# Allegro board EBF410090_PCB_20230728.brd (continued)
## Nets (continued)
VCC5V0_USB30_HOST: C122.1 C123.1 J15.1(VBUS) J15.10(VBUS) U24.1(OUT)
VCC_1V8: C52.1 C57.1 C58.1 C105.1 J30.245(P245) J30.246(P246) L7.2 R37.1 R38.1 U8.8(VCC)
VCC_12V: C1.1 C2.1 C3.1 C12.1 C13.1 C14.1 C21.1 C22.1 C23.1 C31.1 C32.1 C33.1 C38.1 C165.1 C170.1 C171.1 C172.1 D1.2 F1.2 Q4.3(DRAIN) Q12.3(DRAIN) R7.1 R9.1 R14.1 R23.1 R27.1 R196.1 U3.3(VIN) U4.3(VIN) U5.3(VIN) U36.3(VIN)
VCC_RTC: J30.247(P247) J30.248(P248) R51.2
VCCA_1V8: C53.1 J30.239(P239) J30.240(P240) R35.1 R239.2
VCCIO_ACODEC: C55.1 C186.1 C191.1 J30.241(P241) J30.242(P242) R215.1 R217.1
VDD_3V3: C5.1 C6.1 C59.1 C62.1 C69.1 C75.1 C76.1 C90.1 C94.1 C109.1 C127.1 C431.1 D6.2 D19.2 D20.2 J32.1 J34.1 J35.1 J36.1 L5.2 L6.2 LED1.2(ANODE) LED2.2(ANODE) LED3.2(ANODE) Q7.2(SOURCE) R39.1 R42.1 R44.1 R47.2 R52.1 R53.1 R54.1 R55.1 R67.1 R68.1 R69.1 R70.1 R127.1 R152.1 R156.1 R157.1 R159.1 R164.1 R166.1 R168.1 R170.1 U1.1(OUT) U9.5(VCC) U10.5(VCC) U13.16(VCC) U14.8(VCC) U15.8(VCC)
VDD_5V: C10.1 C11.1 D27.2 Q9.1(GATE) U2.1(OUT)
B_DM1: J15.11(D-) R130.1 U18.5(D2-) U18.6(NC4)
B_DM2: J17.8(D-) R139.1 U20.4(D2+) U20.7(NC3)
B_DM3: J17.2(D-) R132.1 U20.1(D1+) U20.10(NC1)
B_DP1: J15.12(D+) R131.1 U18.4(D2+) U18.7(NC3)
B_DP2: J17.9(D+) R140.1 U20.5(D2-) U20.6(NC4)
B_DP3: J17.3(D+) R133.1 U20.2(D1-) U20.9(NC2)
BD_CH3: C56.1 J30.204(P204) R35.2 R36.1
CAM0_NRST: J20.22 J30.25(P25)
CAM0_PWDN: J20.15 J30.26(P26)
CAM0_PWR_EN: J30.6(P6) R180.1
CAM1_NRST: J21.22 J30.23(P23)
CAM1_PWDN: J21.15 J30.16(P16)
CAM1_PWR_EN: J30.49(P49) R187.1
CC1: D26.2 J16.A5(CC1)
CC2: D26.1 J16.B5(CC2)
CSI_RX_D2N_S0: J20.17 R179.2
CSI_RX_D2N_S1: J21.12 R181.2
CSI_RX_D2P_S0: J20.16 R177.2
CSI_RX_D2P_S1: J21.11 R178.2
CSI_RX_D3N_S0: J20.20 R185.2
CSI_RX_D3N_S1: J21.8 R186.2
CSI_RX_D3P_S0: J20.19 R183.2
CSI_RX_D3P_S1: J21.7 R184.2
CTP0_INT: J18.11 J30.30(P30) R163.2
CTP0_RST: J18.12 J30.34(P34) R167.2
CTP1_INT: J19.11 J30.33(P33) R165.2
CTP1_RST: J19.12 J30.31(P31) R169.2
DBG_RX: R41.2 U10.2(A)
DBG_RXD: J6.3 R41.1 Z3.1
DBG_TX: R40.2 U9.4(Y)
DBG_TXD: J6.2 R40.1 Z2.1
DM4: D35.2 J24.36(USB-D-) R213.1
DP4: D36.2 J24.38(USB-D+) R214.1
DSI0_RST: J18.15 J30.24(P24)
DSI0_TE: J30.22(P22) R161.1
DSI1_RST: J19.15 J30.35(P35)
DSI1_TE: J30.37(P37) R162.1
EDP_AUXN: C157.2 J22.10 R192.2
EDP_AUXP: C156.2 J22.9 R189.2
EDP_BL_EN: J22.22 J30.136(P136)
EDP_BL_PWM: J22.23 J30.167(P167)
EDP_HPDIN_M0: J22.17 J30.45(P45)
EDP_PWR_EN: J30.8(P8) R193.1 R198.1
EDP_TP_INT: J23.2 J30.12(P12) R190.2
EDP_TP_RESET: J23.3 J30.14(P14) R191.2
EDP_TX_AUXN: C157.1 J30.209(P209)
EDP_TX_AUXP: C156.1 J30.211(P211)
EDP_TX_D0N: J22.6 J30.225(P225)
EDP_TX_D0P: J22.7 J30.227(P227)
EDP_TX_D1N: J22.3 J30.221(P221)
EDP_TX_D1P: J22.4 J30.223(P223)
EXT_PWR_EN: J30.231(P231) R1.1 R3.1 R19.1 R24.1
FAN: C30.1 Q1.2(SOURCE) R9.2 R10.2 R12.1
FSPI_CLK: J30.218(P218) U8.6(CLK)
FSPI_CS0N: J30.208(P208) U8.1(C\S\)
FSPI_D0: J5.2 J30.210(P210) U8.5(DI/IO0)
FSPI_D1: J30.212(P212) U8.2(DO/IO1)
FSPI_D2: J30.214(P214) R37.2 U8.3(W\P\/IO2)
FSPI_D3: J30.216(P216) R38.2 U8.7(HOLD/IO3)
GMAC1_INT: J30.43(P43) R112.1
GMAC1_MCLKINOUT_M1: J30.58(P58) R113.1 R115.1
GMAC1_MDC_M1: J30.78(P78) R108.2 U16.13(MDC)
GMAC1_MDIO_M1: J30.76(P76) R109.2 U16.14(MDIO)
GMAC1_RSTN: C86.1 J30.155(P155) R119.2 R120.2 U16.12(PHYRSTB)
GMAC1_RXCLK_M1: J30.82(P82) R95.2 R101.1
GMAC1_RXD0_M1: J30.86(P86) R93.2 R96.1
GMAC1_RXD1_M1: J30.88(P88) R94.2 R97.1
GMAC1_RXD2_M1: J30.90(P90) R99.1 R103.1
GMAC1_RXD3_M1: J30.92(P92) R100.1 R104.1
GMAC1_RXDV_CRS_M1: J30.84(P84) R102.1 R105.1
GMAC1_TXCLK_M1: J30.64(P64) U16.20(TXC)
GMAC1_TXD0_M1: J30.72(P72) U16.18(TXD0)
GMAC1_TXD1_M1: J30.70(P70) U16.17(TXD1)
GMAC1_TXD2_M1: J30.68(P68) U16.16(TXD2)
GMAC1_TXD3_M1: J30.66(P66) U16.15(TXD3)
GMAC1_TXEN_M1: J30.62(P62) U16.19(TXCTL)
GPIO2_B7: J30.17(P17) R48.2
GPIO2_C0: J30.39(P39) R49.2
HDMI_5V: C131.1 D27.1 D32.2 Q10.1(GATE) Q11.1(GATE) R158.1 R160.1 U26.18
HDMI_TX0N_PORT: J30.131(P131) U26.9 U28.4(D2+) U28.7(NC3)
HDMI_TX0P_PORT: J30.133(P133) U26.7 U28.5(D2-) U28.6(NC4)
HDMI_TX1N_PORT: J30.135(P135) U26.6 U27.1(D1+) U27.10(NC1)
HDMI_TX1P_PORT: J30.137(P137) U26.4 U27.2(D1-) U27.9(NC2)
HDMI_TX2N_PORT: J30.139(P139) U26.3 U27.4(D2+) U27.7(NC3)
HDMI_TX2P_PORT: J30.141(P141) U26.1 U27.5(D2-) U27.6(NC4)
HDMI_TX_CEC_PORT: D31.2 Q9.3(DRAIN) U26.13
HDMI_TX_HPD_PORT: D28.2 R154.2 R155.1 U26.19
HDMI_TX_HPDIN: J30.126(P126) R154.1
HDMI_TXCLKN_PORT: J30.127(P127) U26.12 U28.1(D1+) U28.10(NC1)
HDMI_TXCLKP_PORT: J30.129(P129) U26.10 U28.2(D1-) U28.9(NC2)
HDMI_TXDDC_SCL_PORT: D30.2 Q10.3(DRAIN) R158.2 U26.15
HDMI_TXDDC_SDA_PORT: D29.2 Q11.3(DRAIN) R160.2 U26.16
HDMITX_CEC_M0: J30.128(P128) Q9.2(SOURCE) R156.2
HDMITX_SCL: J30.132(P132) Q10.2(SOURCE) R157.2
HDMITX_SDA: J30.130(P130) Q11.2(SOURCE) R159.2
HOST1_DM: J15.2(D-) R136.1 U19.4(D2+) U19.7(NC3)
HOST1_DP: J15.3(D+) R137.1 U19.5(D2-) U19.6(NC4)
HP_DET_L: C187.1 J30.4(P4) R218.1
HP_SNS: J25.1 J26.1 J30.224(P224) R219.1 R221.1
HPL_OUT: C189.1 J30.226(P226)
HPR_OUT: C190.1 J30.222(P222)
HUB_3V3: C128.1 C129.1 C130.1 R145.1 R146.1 R152.2 U22.1(OVCUR#) U22.20(VDD3V3)
HUB_DM1: R130.2 U22.11(DM1)
HUB_DM2: R139.2 U22.9(DM2)
HUB_DM3: R132.2 U22.7(DM3)
HUB_DM4: R213.2 U22.5(DM4)
HUB_DP1: R131.2 U22.12(DP1)
HUB_DP2: R140.2 U22.10(DP2)
HUB_DP3: R133.2 U22.8(DP3)
HUB_DP4: R214.2 U22.6(DP4)
I2C0_SCL_PMIC: J30.154(P154) U12.6(SCL)
I2C0_SDA_PMIC: J30.152(P152) U12.5(SDA)
I2C1_SCL: J18.9 J20.6 J30.150(P150) R164.2
I2C1_SDA: J18.10 J20.5 J30.148(P148) R168.2
I2C2_SCL_M1: J30.55(P55) R222.2
I2C2_SDA_M1: J30.61(P61) R233.2
I2C3_SCL_M0: J30.46(P46) R237.2
I2C3_SDA_M0: J30.44(P44) R238.2
I2C4_SCL_M0: J23.4 J30.57(P57)
I2C4_SDA_M0: J23.5 J30.59(P59)
I2C5_SCL_M0: J19.9 J21.6 J30.42(P42) R166.2
I2C5_SDA_M0: J19.10 J21.5 J30.40(P40) R170.2
LCD0_BL_PWM: J18.13 J30.163(P163)
LCD1_BL_PWM: J19.13 J30.161(P161)
MDIN0_PHY: J14.3(TD1-) U16.2(MDIN0)
MDIN1_PHY: J14.7(RD1-) U16.5(MDIN1)
MDIN2_PHY: J14.6(TD2-) U16.7(MDIN2)
MDIN3_PHY: J14.9(RD2-) U16.10(MDIN3)
MDIP0_PHY: J14.2(TD1+) U16.1(MDIP0)
MDIP1_PHY: J14.4(RD1+) U16.4(MDIP1)
MDIP2_PHY: J14.5(TD2+) U16.6(MDIP2)
MDIP3_PHY: J14.8(RD2+) U16.9(MDIP3)
MIC_INN: C188.2 J27.1 J30.232(P232) R220.1 Z10.2
MIC_INP: C188.1 J26.2 J26.3 J26.4 J26.5 J27.2 J30.230(P230) R216.2 Z7.2
MINIPCIE_3V3: C169.1 C173.1 C174.1 C175.1 C181.1 C182.1 C183.1 C184.1 J24.2(VBAT1) J24.24(VBAT5) J24.39(VBAT2) J24.41(VBAT3) J24.52(VBAT4) L10.2 R203.1 R208.1
MINIPCIE_NWDISABLE: J30.173(P173) R211.2
MIPI0_PWR_EN: J30.10(P10) R172.1
MIPI1_PWR_EN: J30.47(P47) R171.1
MIPI_CSI_RX_CLK0N: J20.10 J30.83(P83)
MIPI_CSI_RX_CLK0P: J20.9 J30.85(P85)
MIPI_CSI_RX_CLK1N: J21.10 J30.79(P79)
MIPI_CSI_RX_CLK1P: J21.9 J30.81(P81)
MIPI_CSI_RX_D0N: J20.12 J30.99(P99)
MIPI_CSI_RX_D0P: J20.11 J30.101(P101)
MIPI_CSI_RX_D1N: J20.8 J30.95(P95)
MIPI_CSI_RX_D1P: J20.7 J30.97(P97)
MIPI_CSI_RX_D2N: J30.91(P91) R179.1 R181.1
MIPI_CSI_RX_D2P: J30.93(P93) R177.1 R178.1
MIPI_CSI_RX_D3N: J30.87(P87) R185.1 R186.1
MIPI_CSI_RX_D3P: J30.89(P89) R183.1 R184.1
MIPI_DSI_TX0_CLKN: J18.24 J30.121(P121)
MIPI_DSI_TX0_CLKP: J18.23 J30.123(P123)
MIPI_DSI_TX0_D0N: J18.27 J30.117(P117)
MIPI_DSI_TX0_D0P: J18.26 J30.119(P119)
MIPI_DSI_TX0_D1N: J18.21 J30.113(P113)
MIPI_DSI_TX0_D1P: J18.20 J30.115(P115)
MIPI_DSI_TX0_D2N: J18.18 J30.109(P109)
MIPI_DSI_TX0_D2P: J18.17 J30.111(P111)
MIPI_DSI_TX0_D3N: J18.30 J30.105(P105)
MIPI_DSI_TX0_D3P: J18.29 J30.107(P107)
MIPI_DSI_TX1_CLKN: J19.24 J30.120(P120)
MIPI_DSI_TX1_CLKP: J19.23 J30.122(P122)
MIPI_DSI_TX1_D0N: J19.27 J30.116(P116)
MIPI_DSI_TX1_D0P: J19.26 J30.118(P118)
MIPI_DSI_TX1_D1N: J19.21 J30.114(P114)
MIPI_DSI_TX1_D1P: J19.20 J30.112(P112)
MIPI_DSI_TX1_D2N: J19.18 J30.108(P108)
MIPI_DSI_TX1_D2P: J19.17 J30.110(P110)
MIPI_DSI_TX1_D3N: J19.30 J30.104(P104)
MIPI_DSI_TX1_D3P: J19.29 J30.106(P106)
OTG0_DM: D33.2 J16.A7(DN1) J16.B7(DN2) R134.1
OTG0_DP: D34.2 J16.A6(DP1) J16.B6(DP2) R135.1
PCIE20_CLKREQN_M0: J30.177(P177) R210.1
PCIE20_PERSTN_M0: J30.175(P175) R212.2
PCIE20_REFCLKN: J24.11(VDD-EXT) J30.181(P181)
PCIE20_REFCLKP: J24.13(RESERVED) J30.183(P183)
PCIE20_RXN: J24.23(UART-RXD) J30.187(P187)
PCIE20_RXP: J24.25(UART-RTS) J30.185(P185)
PCIE20_TXN: C179.1 J30.189(P189)
PCIE20_TXP: C180.1 J30.191(P191)
PCIE20_WAKEN_M0: J30.171(P171) R209.1
PCIE_PWREN_EN: J30.149(P149) R206.1
PE_TXN: C179.2 J24.31(UART-TXD)
PE_TXP: C180.2 J24.33(PERST2)
PHY1_LED1: J14.14(YELA) R116.1 U16.33(LED1)
PHY1_LED2: J14.11(GRLA) R117.1 U16.34(LED2)
PHY_CLKOUT125: R113.2 U16.35(CLKOUT)
PWM2_M0: J30.159(P159) R17.1
PWM3_IR: C64.1 J30.165(P165) R46.1
PWR_3V3_EN: J30.36(P36) R31.1
PWR_5V_EN: J30.140(P140) R33.1
PWR_12V_EN: J30.147(P147) R29.1
PWRON_KEY: C60.1 J30.235(P235) SW1.3(B1) SW1.4(B2) Z1.2
RECOVERY: J30.202(P202) R43.2
RESET_KEY: C61.1 J30.233(P233) SW2.3(B1) SW2.4(B2) Z4.2
RS485_1_A: D23.2 J10.1 R71.2 R80.1 U14.6(A)
RS485_1_B: D21.2 R73.1 R76.1 R79.1 U14.7(B)
RS485_2_A: D24.2 J11.1 R72.2 R82.1 U15.6(A)
RS485_2_B: D22.2 R74.1 R78.1 R81.1 U15.7(B)
RX8010_NIRQ1: J30.20(P20) U12.7(/IRQ1)
RX8010_NIRQ2: J30.18(P18) U12.3(/IRQ2)
RXD1_232: D9.2 R58.1 U13.13(R1IN)
RXD2_232: D8.2 R56.1 U13.8(R2IN)
SARADC_VIN1: J30.200(P200) R232.2
SDMMC0_CLK: J30.178(P178) R63.1
SDMMC0_CMD: J30.176(P176) R62.1
SDMMC0_D0: J30.174(P174) R64.1
SDMMC0_D1: J30.172(P172) R65.1
SDMMC0_D2: J30.170(P170) R60.1
SDMMC0_D3: J30.168(P168) R61.1
SDMMC0_DET_L: J30.166(P166) R66.1
SIM_CLK0: J24.12(USIM-CLK) R202.1
SIM_DATA0: J24.10(USIM-DATA) R204.1
SIM_RST0: J24.14(USIM-RST) R201.1
SIM_VDD: J24.8(USIM-VDD) R200.1 U37.1(VCC) U38.1
SPKN_OUT: J30.236(P236) R224.1 Z13.2
SPKP_OUT: J30.238(P238) R223.1 Z11.2
SS_TXN: C114.1 J15.8(TX-) U19.2(D1-) U19.9(NC2)
SS_TXP: C115.1 J15.9(TX+) U19.1(D1+) U19.10(NC1)
TXD1_232: D11.2 R59.1 U13.14(T1OUT)
TXD2_232: D10.2 R57.1 U13.7(T2OUT)
UART1_DIR: J30.184(P184) R75.1 U14.2(R\E\) U14.3(DE)
UART1_RX_M0: J30.194(P194) R69.2 U14.1(RXD)
UART1_TX_M0: J30.196(P196) R67.2 U14.4(TXD)
UART2_RX_M0_DEBUG: J30.156(P156) R42.2 U10.4(Y)
UART2_TX_M0_DEBUG: J30.158(P158) R39.2 U9.2(A)
UART3_RX_M1: J30.52(P52) R52.2 U13.9(R2OUT)
UART3_TX_M1: J30.54(P54) R53.2 U13.10(T2IN)
UART4_RX_M1: J30.48(P48) R54.2 U13.12(R1OUT)
UART4_TX_M1: J30.50(P50) R55.2 U13.11(T1IN)
UART6_DIR: J30.182(P182) R77.1 U15.2(R\E\) U15.3(DE)
UART6_RX_M0: J30.190(P190) R70.2 U15.1(RXD)
UART6_TX_M0: J30.192(P192) R68.2 U15.4(TXD)
UART7_RX_M0: J30.186(P186) R225.2
UART7_TX_M0: J30.188(P188) R234.2
UART9_RX_M1: J30.98(P98) R235.2
UART9_TX_M1: J30.100(P100) R236.2
USB2_HOST2_DM: J30.7(P7) R126.1
USB2_HOST2_DP: J30.9(P9) R125.1
USB2_HOST3_DM: J30.11(P11) R143.2
USB2_HOST3_DP: J30.13(P13) R142.2
USB3_HOST1_DM: J30.3(P3) R136.2
USB3_HOST1_DP: J30.5(P5) R137.2
USB3_HOST1_SSRXN: J15.5(RX-) J30.201(P201) U18.2(D1-) U18.9(NC2)
USB3_HOST1_SSRXP: J15.6(RX+) J30.199(P199) U18.1(D1+) U18.10(NC1)
USB3_HOST1_SSTXN: C114.2 J30.197(P197)
USB3_HOST1_SSTXP: C115.2 J30.195(P195)
USB20_HOST_PWR_EN: J30.28(P28) R141.1
USB20_OTG_PWR_EN: J30.138(P138) R150.1
USB30_HOST_PWR_EN: J30.41(P41) R147.1
USB OTG: C125.1 C126.1 J16.A4(VBUS1) J16.A9(VBUS2) J16.B4(VBUS4) J16.B9(VBUS3) R149.1 U25.1(OUT)
USB_OTG0_DM: J30.203(P203) R134.2
USB_OTG0_DP: J30.205(P205) R135.2
USB_OTG0_ID: J30.160(P160) R138.2
USB_OTG0_VBUSDET: J30.162(P162) R149.2 R151.1
USER_LED: J30.142(P142) R45.2
WLAN_PWR_EN: J30.151(P151) R128.1
N02088: F1.1 J1.4
N03633: C7.1 U3.6(BOOT)
N03641: C7.2 L1.1 U3.2(SW)
N03801: C8.2 R4.2 R6.1 U3.4(FB)
N28501: C28.1 U5.6(BOOT)
N28533: C28.2 L3.1 U5.2(SW)
N15118698: C4.1 R1.2 U1.4(EN)
N15119063: R2.1 U1.3(ISET)
N15122947: C9.1 R3.2 U2.4(EN)
N15123057: R5.1 U2.3(ISET)
N15599533: R96.2 U16.25(RXD0)
N15599537: R97.2 U16.24(RXD1)
N15599541: R99.2 U16.23(RXD2)
N15599545: R100.2 U16.22(RXD3)
N15599549: R101.2 U16.27(RXC)
N15599553: R102.2 U16.26(RXCTL)
N15599792: R90.2 R91.1 R93.1 R94.1 R95.1
N15600759: R106.2 R107.1 R108.1 R109.1
N15600826: R110.2 R112.2 U16.31(INTB)
N15601838: C83.1 U16.37(XTAL_OUT) Y1.1
N15601846: C84.1 U16.36(XTAL_IN) Y1.3
N15602572: R118.1 U16.32(LED0)
N15602600: R117.2 R121.2 R122.1
N15603170: C85.1 J14.1(CT)
N15605512: R98.1 U16.39(RSET)
N15605755: C79.1 C80.1 R89.1 R92.1 U16.28(DVDD_RG)
N15611443: C118.1 R141.2 U21.4(EN)
N15611553: R144.1 U21.3(ISET)
N15653247: C124.1 R150.2 U25.4(EN)
N15653357: R153.1 U25.3(ISET)
N15653957: C121.1 R147.2 U24.4(EN)
N15654067: R148.1 U24.3(ISET)
N15659726: C18.2 R7.2 R8.1 U3.5(EN)
N15752445: L9.1 U26.G1(20) U26.G2(21) U26.G3(22) U26.G4(23)
N15772454: J19.14 R162.2
N15774097: J18.14 R161.2
N15830872: C190.2 J25.3 J25.5 Z9.2
N15830941: C189.2 J25.2 R218.2 Z8.2
N15838979: J25.4 R217.2
N15851038: C185.1 R215.2 R216.1
N15852295: J29.1 R223.2
N15852481: J29.2 R224.2
N15980269: J10.2 R73.2
N16735828: LED1.1(CATHODE) R45.1
N16735933: LED2.1(CATHODE) R48.1
N16793147: D12.2 J9.1(DAT2) R60.2
N16793149: D16.2 J9.7(DAT0) R64.2
N16793151: D15.2 J9.5(CLK) R63.2
N16793153: D14.2 J9.3(CMD) R62.2
N16793155: D13.2 J9.2(CD/DAT3) R61.2
N16793157: D17.2 J9.8(DAT1) R65.2
N16793300: D18.2 J9.9(CD) R66.2
N16795570: LED3.1(CATHODE) R49.1
N16795883: C37.2 R23.2 R24.2 R25.1 U5.5(EN)
N16811933: J24.1(MIC-P) R208.2 R209.2
N16823854: J24.7(SPK-N) R210.2
N16928945: J24.20(W-DISABLE) R211.1
N16929135: J24.22(PERST1) R212.1
N16980859: C178.1 R201.2 U37.2(RST) U38.6
N16980861: C177.1 R202.2 U37.3(CLK) U38.4
N16980863: C176.1 R200.2 R204.2 U37.7(I/O) U38.5
N17405290: C29.2 R20.2 R22.1 U5.4(FB)
N17423559: C19.1 U4.6(BOOT)
N17423580: C19.2 L2.1 U4.2(SW)
N17423608: C27.2 R14.2 R15.1 U4.5(EN)
N17423737: C20.2 R11.2 R13.1 U4.4(FB)
N17430242: R34.1 U7.3(ISET)
N17430314: C47.1 R33.2 U7.4(EN)
N17443353: R32.1 U6.3(ISET)
N17443371: C41.1 R31.2 U6.4(EN)
N17444423: C38.2 Q4.1(GATE) Q5.1(GATE) Q6.3(COLLECTOR) R27.2
N17444523: Q6.1(BASE) R29.2 R30.1
N17454508: C71.2 U13.1(C1+)
N17454513: C71.1 U13.3(C1-)
N17455367: C72.2 U13.4(C2+)
N17455372: C72.1 U13.5(C2-)
N17455499: C70.1 U13.6(V-)
N17455508: C68.1 U13.2(V+)
N17466585: L4.1 U16.30(REG_OUT)
N17592125: C168.1 U36.6(BOOT)
N17592129: C168.2 L10.1 U36.2(SW)
N17592172: C169.2 R203.2 R205.1 U36.4(FB)
N17592286: R206.2 U36.5(EN)
N17633217: C119.1 U22.3(XOUT) Y2.1
N17633237: C120.2 U22.4(XIN) Y2.3
N17633305: R145.2 U22.16(RESET#/CDP)
N17633317: R146.2 U22.18(PSELF)
N17685591: C165.2 Q12.1(GATE) Q13.1(GATE) Q14.3(COLLECTOR) R196.2
N17685601: Q14.1(BASE) R198.2 R199.1
N17685851: Q13.2(SOURCE) R194.2
N17690217: R195.1 U35.3(ISET)
N17690290: C162.1 R193.2 U35.4(EN)
N17695706: C139.1 R172.2 U29.4(EN) U31.4(EN)
N17695791: R175.1 U31.3(ISET)
N17695827: R174.1 U29.3(ISET)
N17697466: J14.13(YELC) R114.1
N17697880: R182.1 U33.3(ISET)
N17697953: C150.1 R180.2 U33.4(EN)
N17701231: J11.2 R74.2
N17702194: J12.3 R81.2
N17702199: J12.4 R82.2
N17702222: J12.2 R80.2
N17702231: J12.1 R79.2
N17728858: D19.1 R71.1
N17729021: D20.1 R72.1
N17731599: J8.6 R59.2
N17731608: J8.4 R58.2
N17731627: J8.1 R56.2
N17748815: Q5.2(SOURCE) R26.2
N17750545: Q1.1(GATE) Q2.3(COLLECTOR) R12.2
N17750554: D2.1(K) J2.1 Q1.3(DRAIN)
N17750632: Q2.1(BASE) R17.2 R18.1
N17759502: C67.1 D6.3 U12.8(VDD)
N17770939: R142.1 U22.15(DPU)
N17770942: R143.1 U22.14(DMU)
N17861933: C65.1 C66.1 R47.1 U11.2(VCC)
N17863087: R44.2 R46.2 U11.3(OUT)
N17946485: C63.1 R43.1 SW3.3(B1) SW3.4(B2) Z5.2
N17975561: D7.2 J7.1 R50.2 R51.1
N18056005: C109.2 Q7.1(GATE) R127.2 R128.2
N18056634: C106.1 C107.1 U17.2(RF0)
N18056637: C106.2 C108.1 CN1.1
N18057325: R126.2 U17.7(D-)
N18057335: R125.2 U17.6(D+)
N18091011: D6.1 R50.1
N18111918: C136.1 R171.2 U30.4(EN) U32.4(EN)
N18111989: R176.1 U32.3(ISET)
N18112037: R173.1 U30.3(ISET)
N18115454: R188.1 U34.3(ISET)
N18115527: C153.1 R187.2 U34.4(EN)
N18173560: J16.C1(SH1) J16.C2(SH2) J16.C3(SH3) J16.C4(SH4) L8.1
N18175084: D26.3 R138.1
N18245213: LED4.1(CATHODE) Q3.3(COLLECTOR)
N18245628: LED4.2(ANODE) R16.2
N18246356: Q3.1(BASE) R19.2 R21.1
N18288623: C192.1 R232.1 R239.1 SW4.3(B1) SW4.4(B2) Z23.2
N18341998: J14.12(GRLC) R111.1
N18348384: J8.3 R57.2
N18386455: Q12.2(SOURCE) R194.1
N18461230: Q4.2(SOURCE) R26.1
N18494968: D48.2 J34.2 R237.1
N18494970: D47.2 J34.3 R238.1
N18495009: D50.2 J32.2 R222.1
N18495011: D49.2 J32.3 R233.1
N18495097: D52.2 J35.2 R234.1
N18495099: D51.2 J35.3 R225.1
N18495175: D54.2 J36.2 R236.1
N18495177: D53.2 J36.3 R235.1

Pads without a net: J6 1; J15 14 15 17 18; J16 A8 B8; J20 13 14; J21 13 14 16 17 18 19 20 21; J22 1 14 24 25 30; J24 3 5 6 16 17 19 28 30 32 42 44 45 46 47 48 49 51; J30 19 21 27 29 32 51 65 67 69 71 73 75 96 153 213 215 217 219; NOREF#2 1; NOREF#4 1; NOREF#5 1; NOREF#8 1; NOREF#9 1; NOREF#10 1; NOREF#11 1; NOREF#12 1; U12 1 2; U17 3 4 9 10 11 12 13 14; U22 2 13 17 19 21 22 23 24; U26 14; U37 4 6; U38 3

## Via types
v1: diameter 0.508, hole 0.305, TOP to BOTTOM, 1260 vias

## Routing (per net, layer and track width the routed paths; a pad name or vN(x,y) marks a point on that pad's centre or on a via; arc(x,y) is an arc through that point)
1V05_AVDD_PHY: length 27.4
  TOP w0.305: v1(67.94,37.43) 67.91,37.43 67.26,36.78 67.26,34.57 66.65,33.96 63.17,33.96 62.56,34.57 62.56,38.43 61.75,39.23 C100.1 v1(61.72,40.04) 61.02,40.74 60.38,40.74 60.08,41.05 C101.1 ; C101.1 C99.1 59.44,45.46 59.43,45.46 v1(59.4,45.46) ; C101.1 v1(59.4,43.43)
  BOTTOM w0.203: v1(59.4,45.46) 59.44,45.46 59.45,45.45 U16.8 ; U16.3 59.46,43.45 59.44,43.43 v1(59.4,43.43) ; v1(61.72,40.04) 61.72,40.38 61.87,40.53 U16.38
  BOTTOM w0.305: R124.2 v1(67.94,37.43) C102.1
1V05_DVDD_PHY: length 13.1
  TOP w0.305: v1(68.96,37.43) 68.96,37.46 67.31,39.11 67.31,42.95 66.45,43.81 C95.1 C96.1 C97.1 66.41,46.47 v1(66.55,46.61)
  BOTTOM w0.203: v1(66.55,46.61) 66.19,46.25 U16.21
  BOTTOM w0.305: C98.1 v1(68.96,37.43) R123.1
1V8_DVDD_PHY: length 34.9
  ART03 w0.305: v1(59.33,51.56) 66.88,51.56 67.16,51.28 67.16,50.27 v1(66.55,49.66)
  BOTTOM w0.305: L7.1 75.65,48.39 C103.1 ; C103.1 C104.1 R90.1 76.02,46.35 76.33,46.05 76.33,39.42 76.02,39.11 R89.2 ; C103.1 74.41,48.42 73.71,49.12 67.97,49.12 67.44,49.66 v1(66.55,49.66) 66.29,49.66 65.41,50.54 R106.1 ; R119.1 v1(59.33,51.56)
3V3_AVDD_PHY: length 16.8
  TOP w0.305: v1(60.71,40.04) 59.17,40.04 58.67,40.54 58.67,45.59 59.82,46.73 C93.1 59.33,47.49 v1(59.33,48)
  BOTTOM w0.203: v1(59.33,48) 60.45,48 61.06,47.39 U16.11 ; U16.40 61.06,41 60.71,40.64 v1(60.71,40.04)
  BOTTOM w0.305: v1(60.71,40.04) 60.48,40.04 59.56,39.12 C92.1
3V3_DVDD_PHY: length 61.9
  TOP w0.381: R122.2 64.26,35.23 64.57,34.92 v1(65.28,34.92) 65.43,34.92 66.55,36.04 v1(66.55,37.43) 66.55,37.46 66.41,37.6 C88.1 C89.1 66.41,42.79 v1(66.55,42.92)
  ART03 w0.305: v1(66.55,50.67) 66.19,51.03 59.81,51.03 v1(59.33,50.54)
  ART04 w0.305: v1(66.55,42.92) 67.11,43.49 67.11,50.11 v1(66.55,50.67)
  ART04 w0.381: v1(75.18,45.34) 74.63,44.78 74.63,39.83 73.86,39.06 67.31,39.06 66.55,38.3 v1(66.55,37.43)
  BOTTOM w0.203: v1(66.55,42.92) 66.42,43.05 U16.29
  BOTTOM w0.305: R107.2 65.46,51.56 66.34,50.67 v1(66.55,50.67) ; R92.2 75.51,40.13 75.82,40.44 75.82,45.03 75.51,45.34 v1(75.18,45.34) R91.2 ; R118.2 v1(65.28,34.92) 65.91,34.29 69.33,34.29 69.98,34.94 C87.1 70.01,35.69 70.51,36.19 L5.1 ; R110.1 v1(66.55,37.43) ; R120.1 v1(59.33,50.54)
3V3_EDP: length 17.2
  TOP w0.305: v1(63.75,16.25) R190.1 ; R189.1 125.51,22.6 v1(125.45,22.67) ; J22.12 131.36,25.43 v1(131.61,25.68) 131.36,25.93 J22.13 ; R191.1 v1(66.29,16.25)
  ART04 w0.762: 60.01,13.65 J23.1
  BOTTOM w0.508: v1(125.45,22.67) 126.4,22.67 127.01,23.27 127.01,25.07 127.62,25.68 v1(131.61,25.68)
  vias: v1(73.79,17.27) v1(74.8,17.27) v1(132.61,25.68)
3V3_IMAGE_1: length 8.7
  TOP w0.305: R163.1 v1(125.43,69.85) ; J18.5 v1(131.02,66.12)
  ART04 w0.305: v1(125.43,69.85) 125.98,69.29 125.98,66.24 v1(125.35,65.61)
  BOTTOM w0.305: R167.1 130.68,65.78 v1(131.02,66.12)
3V3_IMAGE_2: length 16.5
  TOP w0.203: v1(119.83,48.46) 120.39,49.02 R165.1
  TOP w0.305: C145.1 v1(127.91,43.7) ; R169.1 v1(125.43,47.88)
  ART03 w0.508: v1(125.43,47.88) 126.36,47.88 126.97,47.27 126.97,44.64 v1(127.91,43.7)
  BOTTOM w0.203: v1(125.43,47.88) 124.84,48.46 121.62,48.46 121.11,47.95 120.34,47.95 v1(119.83,48.46)
3V3_OUT: length 7.1
  BOTTOM w0.381: J3.5 2.63,35.82 C43.1 C42.1 7.94,35.75 U6.1
3V3_WLAN: length 7.6
  TOP w0.381: U17.8 95.73,36.64 95.12,36.03 C111.1 C110.1 93.68,35.72 Q7.3
5V0_CAM_1: length 17.6
  TOP w0.381: v1(128.93,58.89) v1(127.93,58.89) 127.46,58.43 C152.1 C151.1 126.12,58.36 U33.1
  ART03 w0.305: v1(128.93,67.55) v1(127.93,67.55) 127.14,67.55 126.53,66.94 126.53,59.5 127.14,58.89 v1(127.93,58.89) v1(128.93,58.89)
5V0_CAM_2: length 0.7
  TOP w0.305: C155.1 v1(127.91,36.33)
  vias: v1(128.91,36.33)
5V_OUT: length 7.1
  BOTTOM w0.305: C49.1 C48.1 7.93,39.69 U7.1
  BOTTOM w0.381: J3.3 2.57,39.63 C49.1
12V_EDP: length 8.4
  TOP w0.305: J22.28 127.88,33.43 ; 127.88,33.93 J22.29 ; J22.26 127.88,32.43 ; J22.27 127.88,32.93
12V_OUT: length 8
  BOTTOM w0.508: Q5.3 8.17,44.07 C39.1 6.65,44.61 C40.1 3.13,44.31 J3.1
GND: length 2698.3
  TOP w0.173: v1(0.79,64.84) v1(0.79,57.22)
  TOP w0.203: v1(27.69,65.53) 28.42,65.53 29.68,64.27 31.35,64.27 31.6,64.51 v1(31.6,64.95) ; v1(125.98,73.79) 125.98,73.02 123.62,70.66 118.86,70.66 J24.54 ; J30.94 v1(57.26,52.58) ; J30.74 v1(62.26,52.58)
  TOP w0.305: J30.102 v1(55.26,52.58) 55.26,51.58 54.61,50.93 54.61,46.14 v1(54.05,45.58) ; J30.146 v1(42.26,52.58) ; R199.2 120.27,28.07 v1(120.27,27.56) ; v1(27.69,65.53) 27.01,64.86 J30.207 v1(27.01,60.78) ; v1(26.91,34.42) 26.91,51.17 27.26,51.52 J30.206 ; v1(4.7,57.33) 5.21,56.82 C18.1 R8.2 ; J24.54 118.85,68.53 117.97,67.66 117.97,66.42 117.57,66.01 117.18,66.01 117.18,66.01 116.22,66.01 116.22,66.01 v1(108.43,66.01) 108.32,66.01 106.91,64.6 106.91,61.77 106.71,61.57 ; J18.16 v1(131.75,71.62) ; v1(39.51,60.78) 39.51,60.78 J30.157 ; J22.16 v1(131.61,27.43) 131.61,27.23 131.3,26.93 J22.15 ; U31.2 v1(123.19,67.44) ; J18.28 v1(131.6,77.62) ; v1(59.76,74.18) 59.72,74.18 55.75,70.2 v1(55.47,70.2) 55.14,70.2 54.84,69.9 54.84,67.49 55.45,66.88 56.62,66.88 57.05,66.45 57.05,64.62 57.02,64.59 ; J22.19 v1(131.61,28.93) ; v1(124.45,25.59) 123.89,25.03 123.89,23.22 v1(124.45,22.67) ; v1(124.45,25.59) 123.56,26.48 Q14.2 ; v1(124.45,25.59) v1(125.45,25.59) 125.51,25.65 R192.1 ; J30.220 v1(23.76,55.55) 22.17,55.55 21.76,55.15 J30.228 ; D30.1 v1(67.4,66.67) ; v1(3.16,45.08) 3.17,45.1 C192.2 ; J30.103 55.01,63.46 55.51,63.96 v1(55.51,64.88) 55.01,65.38 49.94,65.38 49.51,64.95 v1(49.51,63.75) J30.125 ; 128.82,73.4 129.1,73.12 J18.19 v1(131.75,73.12) ; 128.82,73.4 128.63,73.21 127.55,73.21 127.22,72.89 127.22,72.59 124.02,69.39 121.37,69.39 119.2,67.22 119.2,65.58 118.34,64.72 115.11,64.72 114.8,64.41 ; 128.82,73.4 128.82,74.59 v1(128.86,74.62) ; 97.23,89.21 97.26,89.19 97.26,88.19 96.8,87.73 95.5,87.73 95.25,87.48 v1(95.25,83.69) v1(93.6,83.69) v1(91.69,83.69) 90.13,82.13 J15.4 89.82,80.37 87.06,77.61 J15.20 86.39,76.02 86.39,73.43 v1(86.92,72.9) ; R176.2 v1(127.91,44.7) ; J24.18 v1(106,61.57) 106.71,61.57 ; J30.144 v1(44.76,52.58) ; 106.71,61.57 106.83,61.44 106.83,57.19 106.47,56.82 100.3,56.82 99.94,57.19 v1(99.94,58.7) D35.1 ; R115.2 63.86,42.66 v1(63.86,43.45) ; v1(128.86,74.62) 128.86,77.87 128.06,78.67 128.06,79.53 v1(128.65,80.12) ; v1(128.86,74.62) J18.22 ; 1.2,55.63 Z5.1 C63.2 ; J30.134 v1(47.26,52.58) v1(47.26,51.58) 47.26,50.19 47.57,49.88 51.08,49.88 51.38,49.58 v1(51.38,48.83) 50.83,48.27 50.83,46.48 v1(51.38,45.92) ; J19.8 v1(131.55,45.53) ; J30.234 20.26,56.72 v1(20.32,56.78) ; C100.2 61.72,37.59 61.59,37.46 v1(61.59,37.43) ; J24.29 v1(101.6,69.77) ; v1(98.4,72.77) 97.77,73.4 96.64,73.4 v1(96,72.77) ; v1(98.4,72.77) 99.04,73.4 101.77,73.4 v1(102.4,72.77) ; v1(98.4,72.77) J24.37 ; v1(19.81,64.51) 19.51,64.22 J30.237 ; J30.53 67.51,61.07 67.94,60.64 67.94,60.35 v1(68.51,59.78) ; v1(123.19,62.61) U29.2 v1(125.35,62.61) ; v1(114.8,61.57) J24.4 114.8,64.41 ; v1(89.17,88.39) 89.17,89.17 89.13,89.21 ; J19.28 128.92,55.53 v1(128.91,55.51) 128.89,55.53 v1(120.14,55.53) ; J30.2 v1(80.26,52.65) 86.79,52.65 v1(87.33,53.19) v1(91.62,53.19) 92.4,53.97 C184.2 v1(93.13,58.17) ; D52.1 v1(98.17,19.18) ; C56.2 v1(27.56,48.98) ; v1(23.35,35.45) 23.37,35.46 v1(23.37,37.46) ; v1(131.63,52.39) 131.5,52.53 J19.22 v1(128.91,52.53) v1(120.14,52.53) ; v1(124.45,22.67) 125.19,21.93 J22.5 ; v1(124.45,22.67) 123.75,21.96 123.75,20.02 124.05,19.71 v1(124.46,19.71) 125.17,20.43 J22.2 ; C53.2 v1(27.56,43.16) ; v1(59.82,78.1) 59.82,77.97 57.62,75.78 57.62,75.45 55.93,73.76 v1(55.47,73.76) ; U28.8 v1(53.34,71.98) ; J30.180 v1(33.76,52.58) ; U17.5 v1(100.69,27.81) ; 85.67,62.74 85.72,62.69 v1(85.72,61.43) ; 85.67,62.74 v1(82.04,62.74) ; 85.67,62.74 87.63,64.7 87.63,68.75 J24.53 v1(89.55,73.39) 95.38,73.39 v1(96,72.77) ; J30.15 77.01,63.75 v1(77.01,63.75) 78.59,63.75 80.37,65.53 84.33,65.53 85.26,66.46 85.26,74.23 84.22,75.27 84.22,77.33 J14.15 87.06,81.59 J15.19 88.29,82.37 91.01,85.09 93,85.09 v1(93.6,85.69) 93.6,87.1 92.99,87.71 92.99,89.19 92.96,89.21 ; v1(125.45,37.21) U34.2 v1(123.18,37.21) ; R188.2 v1(127.91,38.33) ; J22.18 v1(128.74,28.43) ; v1(4.19,59.16) 4.26,59.09 SW3.2 ; Z23.1 v1(2.16,45.08) ; v1(4.19,63.78) C37.1 ; R220.2 v1(41.27,64.9) ; v1(86.92,72.9) 86.39,72.36 86.39,65.46 85.09,64.16 80.82,64.16 80.51,63.85 v1(80.51,63.75) 80.51,63.75 J30.1 ; v1(86.92,72.9) 86.92,73.11 88.61,74.8 92.76,74.8 J15.16 94.51,74.79 98.3,74.79 J15.21 102.6,79.08 102.6,83.8 98.54,87.86 v1(98.54,88.38) ; v1(101.73,88.39) 101.73,86.61 103.89,84.45 103.89,74.25 v1(102.4,72.77) ; J30.198 v1(29.26,52.58) ; R151.2 v1(38.35,48.98) ; J22.21 v1(131.61,29.93) ; v1(26.41,88.87) 26.41,88.38 v1(29.31,85.47) 29.84,86 33.89,86 v1(34.21,85.67) 33.88,85.35 33.88,76.25 v1(34.21,75.92) 34.21,68.9 v1(33.51,68.21) 33.51,67.55 31.6,65.63 v1(31.6,64.95) ; C27.1 R15.2 ; D31.1 v1(67.4,65.4) 67.51,65.29 ; J30.77 61.51,60.78 v1(61.51,60.78) ; D51.1 v1(100.2,19.18) ; U30.2 v1(125.45,40.51) ; R36.2 v1(27.56,46.57) ; v1(120.14,51.03) v1(128.91,51.03) J19.19 v1(131.57,51.03) ; v1(96,72.77) J24.43 ; J30.56 v1(66.76,52.58) ; D48.1 v1(86.49,17.65) ; v1(29.42,88.87) 29.42,87.72 30.02,87.13 34.73,87.13 35.44,86.41 35.44,85.77 v1(35.54,85.67) 35.44,85.57 35.44,82.11 v1(36.02,81.53) 35.44,80.96 35.44,76.02 v1(35.54,75.92) 35.44,75.82 35.44,67.18 v1(34.01,65.75) 33.45,65.19 33.45,64.31 v1(34.01,63.75) J30.179 ; Z10.1 v1(42.03,68.2) ; J30.193 30.51,61.07 30.57,61.01 30.57,59.34 v1(30.01,58.78) ; J30.261 80.11,45.35 v1(78.24,45.35) ; J22.11 v1(128.74,24.93) ; v1(114.97,58.17) C183.2 ; v1(53.34,75.49) U27.8 U27.3 v1(55.63,75.49) 55.65,75.49 56.62,76.45 56.62,81.18 v1(56.9,81.46) ; J30.164 v1(37.76,52.58) ; J18.25 v1(131.75,76.12) ; C1.2 v1(16.64,72.97) ; C120.1 126.82,77.47 127.13,77.16 127.13,74.99 126.82,74.69 Y2.2 125.99,73.79 v1(125.98,73.79) 125.86,73.66 122.99,73.66 122.68,73.96 122.68,75.31 123.56,76.19 Y2.4 123.33,76.55 C119.2 123.33,77.84 v1(122.94,78.23) ; J22.8 v1(131.22,23.43) ; v1(118.83,48.46) 120.11,49.74 128.69,49.74 v1(128.91,49.53) J19.16 131.07,49.53 v1(131.57,50.03) ; D36.1 v1(96.91,58.7) 96.91,56.81 98.03,55.69 107.21,55.69 108.43,56.91 v1(108.43,57.45) 108.43,64.34 108.81,64.72 114.5,64.72 114.8,64.41 ; v1(42.51,60.78) 42.51,60.78 J30.145 ; J22.20 v1(128.74,29.43) ; v1(102.4,72.77) J24.27 ; v1(56.95,82.78) 55.85,82.78 55.24,82.17 55.24,77.7 54.64,77.09 v1(53.44,77.09) 53.43,77.1 52.82,77.1 45.01,69.29 v1(45.01,63.75) J30.143 ; v1(120.14,57.03) 132.01,57.03 v1(132.38,57.4) ; D29.1 v1(67.4,69.21) ; J30.169 v1(36.51,60.78) ; J24.21 v1(104.8,72.77) ; J24.9 v1(112.8,72.77) ; CN1.2 v1(106.28,19.05) ; C136.2 v1(124.31,42.92) ; CN1.3 v1(103.27,19.05) ; Z1.1 C60.2 ; J30.38 v1(71.26,52.58) ; v1(21.51,60.78) J30.229 21.51,64.22 v1(21.81,64.51) ; J30.124 v1(49.76,55.55) ; C138.2 v1(127.91,40.63) ; v1(59.92,76.4) 59.81,76.4 58.8,75.4 58.8,74.93 55.85,71.98 v1(55.63,71.98) U28.3 ; C153.2 v1(116.46,38.16) ; J24.15 v1(110.4,72.77) ; J24.50 v1(93.2,61.57) ; J24.40 v1(97.2,61.57) ; J30.63 65.01,60.78 v1(65.01,60.78) ; J30.251 v1(16.01,64.01) ; J24.35 v1(99.2,69.77) ; C145.2 v1(127.91,42.7) ; v1(102.27,58.17) C181.2 ; Z7.1 C186.2 v1(37.2,67.44) 37.2,66.67 C185.2 ; C155.2 v1(127.91,37.33) ; J24.34 v1(99.6,61.57) ; D50.1 v1(76.58,16) ; D47.1 v1(87.76,17.65) ; v1(120.14,54.03) J19.25 ; Z4.1 C61.2 ; D28.1 v1(67.4,67.94) ; J19.6 v1(131.55,44.53) ; C150.2 v1(116.75,60.26) ; D49.1 v1(81.06,16) ; J24.26 v1(102.8,61.57)
  TOP w0.381: v1(132.38,57.4) 132.68,57.7 J19.31 v1(132.68,59.89) ; 98.55,89.21 98.55,88.39 v1(98.54,88.38) ; J22.31 v1(132.68,35.15) ; J22.32 v1(132.68,19.21) ; v1(85.09,19.43) v1(85.09,18.29) C431.2 ; U11.1 v1(122.95,10.3) ; SW4.1 5.34,53.59 ; v1(132.68,41.31) J19.32 v1(132.68,38.44) ; v1(101.73,88.39) 101.73,89.21 ; SW4.2 5.35,49.29 ; U11.4 v1(126.76,10.3)
  TOP w0.508: U32.2 120.88,45.34 v1(120.83,45.39) v1(119.83,45.39) ; v1(67.37,89.21) v1(66.37,89.21) v1(65.37,89.21) v1(61.56,89.21) v1(57.75,89.21) v1(53.94,89.21) v1(50.13,89.21) v1(46.32,89.21) v1(42.51,89.21) v1(38.7,89.21) v1(34.89,89.21) ; 3.05,26.57 J6.4 ; J6.4 2.14,27.47 ; J6.4 3.05,28.37 ; J6.4 3.95,27.47 ; J3.6 2.51,34.42 ; J3.6 2.51,32.97 ; J3.6 1.78,33.69 ; J3.6 3.24,33.69 ; 19.35,86.54 J1.5 ; J1.5 20.03,87.92 ; J1.5 18.67,87.92 ; 18.13,75.33 J7.2 18.75,74.7 ; v1(136.21,79.43) v1(136.21,75.62) v1(136.21,71.81) v1(136.21,69) v1(136.21,64.19) v1(136.21,60.38) v1(136.21,56.57) ; 1.78,41.69 J3.2 ; J3.2 3.24,41.69 ; J3.2 2.51,40.97 ; J3.2 2.51,42.42 ; J1.3 18.5,82.14 ; J1.3 17.77,80.66 ; J1.3 19.23,80.66 ; J1.3 18.5,79.19 ; 26.65,16.13 J8.2 ; J8.2 28.81,16.13 ; J8.2 27.73,17.21 ; J8.2 27.73,15.05 ; v1(103.47,89.21) v1(107.28,89.21) v1(111.09,89.21) v1(114.9,89.21) v1(122.52,89.21) ; J1.2 13.93,80.66 ; J1.2 13.2,82.14 ; J1.2 12.47,80.66 ; J1.2 13.2,79.19 ; v1(121.57,8.79) v1(117.76,8.79) v1(113.95,8.79) v1(110.14,8.79) v1(106.33,8.79) v1(102.52,8.79) v1(98.71,8.79) v1(94.9,8.79) v1(91.09,8.79) v1(87.28,8.79) v1(83.47,8.79) v1(79.66,8.79) v1(75.85,8.79) v1(72.04,8.79) v1(68.23,8.79) v1(64.42,8.79) v1(60.61,8.79) v1(56.8,8.79) v1(52.99,8.79) v1(49.18,8.79) v1(45.37,8.79) v1(41.56,8.79) v1(37.75,8.79) v1(33.94,8.79) v1(30.13,8.79) v1(26.32,8.79) v1(22.51,8.79) v1(18.7,8.79) v1(14.89,8.79) v1(11.08,8.79) v1(7.27,8.79) 7.24,8.79 ; 22.63,74.35 J2.2 ; J2.2 22.63,75.76 ; J2.2 21.93,75.05 ; v1(0.79,55.22) v1(0.79,54.41) v1(0.79,53.41) v1(0.79,52.6) v1(0.79,51.6) v1(0.79,50.6) v1(0.79,49.6) v1(0.79,48.79) v1(0.79,47.79) v1(0.79,46.79) v1(0.79,45.79) v1(0.79,41.98) v1(0.79,38.17) v1(0.79,34.36) v1(0.79,30.55) v1(0.79,26.74) v1(0.79,22.93) v1(0.79,19.12) v1(0.79,15.31) 0.79,15.24 ; 15.71,19.39 SS6.1 ; SS6.1 15.71,25.95 ; SS6.1 18.99,22.67 ; SS6.1 12.43,22.67 ; J3.4 2.51,38.42 ; J3.4 1.78,37.69 ; J3.4 3.24,37.69 ; J3.4 2.51,36.97 ; v1(0.79,64.84) v1(0.79,68.65) v1(0.79,72.46) ; v1(136.21,48.95) v1(136.21,45.14) v1(136.21,41.33) v1(136.21,37.52) v1(136.21,33.71) v1(136.21,29.9) v1(136.21,26.09) v1(136.21,22.28) v1(136.21,18.47) ; 9.55,86.54 J1.1 ; J1.1 8.87,87.92 ; J1.1 10.23,87.92 ; C37.1 R25.2 ; v1(132.68,59.89) J18.32 135.53,61.97 ; v1(99.66,89.21) v1(95.85,89.21) v1(92.04,89.21) v1(88.23,89.21) v1(84.42,89.21) ; 26.16,30.52 J5.1 ; J5.1 25.18,31.49 ; J5.1 26.16,32.47 ; J5.1 27.14,31.49 ; 15.22,16.13 J8.5 ; J8.5 17.38,16.13 ; J8.5 16.3,15.05 ; J8.5 16.3,17.21 ; v1(0.79,57.22) v1(0.79,56.22)
  TOP w0.762: J32.4 82.01,9.55 ; J17.6 118.85,75.14 J24.54 ; J34.4 94.01,9.56 ; J35.4 106.01,9.75 ; J36.4 118.01,9.83
  TOP w1.524: J30.262 13.34,43
  GND02 w0.508: SS6.1 15.71,25.45 ; SS6.1 15.71,19.89 ; SS6.1 18.49,22.67 ; SS6.1 12.93,22.67 ; J5.1 26.16,32.47 ; J5.1 26.16,30.52 ; J5.1 25.18,31.49 ; J5.1 27.14,31.49 ; J17.12 119.2,82.77 ; J17.12 120.68,81.29 ; J17.12 117.72,81.29 ; J17.12 119.2,79.81 ; J15.20 88.84,76.69 ; J15.20 87.06,74.91 ; J15.20 87.06,78.47 ; J15.20 85.28,76.69 ; J17.6 119.2,76.97 ; J17.6 117.72,75.49 ; J17.6 119.2,74.01 ; J17.6 120.68,75.49 ; J36.4 118.74,10.67 ; J36.4 118.01,9.94 ; J36.4 118.01,11.4 ; J36.4 117.28,10.67 ; 108.17,78.49 J17.10 ; J17.10 109.15,79.47 ; J17.10 110.13,78.49 ; J17.10 109.15,77.51 ; 27.73,15.05 J8.2 ; J8.2 28.81,16.13 ; J8.2 27.73,17.21 ; J8.2 26.65,16.13 ; 105.28,10.67 J35.4 ; J35.4 106.01,11.4 ; J35.4 106.01,9.94 ; J35.4 106.74,10.67 ; J17.5 106.1,76.97 ; J17.5 106.1,74.01 ; J17.5 104.62,75.49 ; J17.5 107.58,75.49 ; U26.17 59.33,72.21 ; U26.11 59.17,75.68 ; 100.2,80.59 J15.22 ; J15.22 98.42,82.37 ; J15.22 100.2,84.15 ; J15.22 101.98,82.37 ; J34.4 94.74,10.67 ; J34.4 94.01,9.94 ; J34.4 94.01,11.4 ; J34.4 93.28,10.67 ; SS5.1 81.09,22.67 ; SS5.1 75.53,22.67 ; SS5.1 78.31,25.45 ; SS5.1 78.31,19.89 ; J23.6 70.74,10.67 ; J23.6 70.01,11.4 ; J23.6 70.01,9.94 ; J23.6 69.28,10.67 ; 8.87,87.92 J1.1 ; J1.1 9.55,86.54 ; J1.1 10.23,87.92 ; 13.2,79.19 J1.2 ; J1.2 12.47,80.66 ; J1.2 13.93,80.66 ; J1.2 13.2,82.14 ; 82.01,9.94 J32.4 ; J32.4 82.74,10.67 ; J32.4 81.28,10.67 ; J32.4 82.01,11.4 ; 87.06,80.59 J15.19 ; J15.19 88.84,82.37 ; J15.19 85.28,82.37 ; J15.19 87.06,84.15 ; 61.84,81.46 U26.2 62.42,80.88 ; 109.15,74.51 J17.4 ; J17.4 109.15,76.47 ; J17.4 108.17,75.49 ; J17.4 110.13,75.49 ; J1.5 20.03,87.92 ; J1.5 19.35,86.54 ; J1.5 18.67,87.92 ; 18.5,79.19 J1.3 ; J1.3 19.23,80.66 ; J1.3 17.77,80.66 ; J1.3 18.5,82.14 ; 90.13,76.44 J15.13 ; J15.13 89.4,77.17 ; J15.13 90.86,77.17 ; J15.13 90.13,77.9 ; J15.21 101.98,76.69 ; J15.21 100.2,78.47 ; J15.21 100.2,74.91 ; J15.21 98.42,76.69 ; J2.2 23.33,75.05 ; J2.2 21.93,75.05 ; J2.2 22.63,74.35 ; J2.2 22.63,75.76 ; J15.7 93.63,79.6 ; J15.7 94.36,78.87 ; J15.7 92.9,78.87 ; J15.7 93.63,78.14 ; 1.78,41.69 J3.2 ; J3.2 3.24,41.69 ; J3.2 2.51,40.97 ; J3.2 2.51,42.42 ; J3.4 2.51,38.42 ; J3.4 1.78,37.69 ; J3.4 2.51,36.97 ; J3.4 3.24,37.69 ; J8.5 17.38,16.13 ; J8.5 16.3,15.05 ; J8.5 15.22,16.13 ; J8.5 16.3,17.21 ; 90.13,79.64 J15.4 ; J15.4 90.86,80.37 ; J15.4 90.13,81.1 ; J15.4 89.4,80.37 ; 104.62,81.29 J17.11 ; J17.11 106.1,82.77 ; J17.11 106.1,79.81 ; J17.11 107.58,81.29 ; 89.32,19.12 SS2.1 ; SS2.1 92.1,21.9 ; SS2.1 94.88,19.12 ; SS2.1 92.1,16.34 ; SS1.1 116.3,21.9 ; SS1.1 116.3,16.34 ; SS1.1 119.08,19.12 ; SS1.1 113.52,19.12 ; J15.16 93.63,76.4 ; J15.16 93.63,74.94 ; J15.16 92.9,75.67 ; J15.16 94.36,75.67 ; 3.05,26.57 J6.4 ; J6.4 2.14,27.47 ; J6.4 3.05,28.37 ; J6.4 3.95,27.47 ; J7.2 18.75,74.7 ; J7.2 18.13,75.33 ; J7.2 18.13,74.07 ; U26.5 59.87,79.14 ; 1.78,33.69 J3.6 ; J3.6 3.24,33.69 ; J3.6 2.51,34.42 ; J3.6 2.51,32.97 ; U26.8 63.81,77.42
  GND02 w1.016: J14.15 85.15,78.04 ; J14.10 66.41,74.74 ; J14.16 65.6,78.04
  ART03 w0.203: 23.8,56.94 23.14,56.28 23.14,54.93 ; 23.8,56.94 23.8,55.59 v1(23.76,55.55) 23.14,54.93 ; 23.8,56.94 23.8,64.05 25.64,65.89 27.33,65.89 v1(27.69,65.53) 28.48,66.33 28.48,68.17 v1(28.46,68.2) 28.45,68.21 v1(28.45,70.13) ; 23.14,54.93 23.14,50.71 22.23,49.8 22.23,49.3 v1(21.51,48.58) ; 21.51,52.58 21.72,52.79 21.72,56.86 22.38,57.52 22.38,59.92 v1(21.51,60.78) 22.38,61.65 22.38,64.64 25.23,67.49 26.06,67.49 26.45,67.87 v1(26.45,70.13)
  ART03 w0.305: v1(121.57,8.79) v1(117.76,8.79) v1(113.95,8.79) v1(110.14,8.79) v1(106.33,8.79) v1(102.52,8.79) v1(98.71,8.79) v1(94.9,8.79) v1(91.09,8.79) v1(87.28,8.79) v1(83.47,8.79) v1(79.66,8.79) v1(75.85,8.79) v1(72.04,8.79) v1(68.23,8.79) v1(64.42,8.79) v1(60.61,8.79) v1(56.8,8.79) v1(52.99,8.79) v1(49.18,8.79) v1(45.37,8.79) v1(41.56,8.79) v1(37.75,8.79) v1(33.94,8.79) v1(30.13,8.79) v1(26.32,8.79) v1(22.51,8.79) v1(18.7,8.79) v1(14.89,8.79) v1(11.08,8.79) v1(7.27,8.79) 7.24,8.79 ; v1(28.45,70.13) 28.96,70.63 28.96,71.34 28.46,71.83 26.43,71.83 25.94,71.34 25.94,70.63 v1(26.45,70.13) ; 136.21,15.24 v1(136.21,18.47) v1(136.21,22.28) v1(136.21,26.09) v1(136.21,29.9) v1(136.21,33.71) v1(136.21,37.52) v1(136.21,41.33) v1(136.21,45.14) v1(136.21,48.95) v1(136.21,56.57) v1(136.21,60.38) v1(136.21,64.19) v1(136.21,69) v1(136.21,71.81) v1(136.21,75.62) v1(136.21,79.43) 136.21,82.73 ; v1(0.79,26.74) v1(0.79,30.55) v1(0.79,34.36) v1(0.79,38.17) v1(0.79,41.98) v1(0.79,45.79) v1(0.79,46.79) v1(0.79,47.79) v1(0.79,48.79) v1(0.79,49.6) v1(0.79,50.6) v1(0.79,51.6) v1(0.79,52.6) v1(0.79,53.41) v1(0.79,54.41) v1(0.79,55.22) v1(0.79,56.22) v1(0.79,57.22) v1(0.79,64.84) v1(0.79,68.65) v1(0.79,72.46) ; v1(38.7,89.21) v1(42.51,89.21) ; 21.51,52.58 20.95,52.02 20.95,49.14 v1(21.51,48.58) ; v1(53.94,89.21) v1(57.75,89.21) v1(61.56,89.21) v1(65.37,89.21) v1(66.37,89.21) v1(67.37,89.21) v1(84.42,89.21) v1(88.23,89.21) v1(92.04,89.21) v1(95.85,89.21) v1(99.66,89.21) v1(103.47,89.21) v1(107.28,89.21) v1(111.09,89.21) v1(114.9,89.21) v1(122.52,89.21) 129.73,89.21 ; v1(0.79,22.93) v1(0.79,19.12) v1(0.79,15.31) 0.79,15.24
  ART03 w0.508: 93.28,10.67 J34.4 ; J34.4 94.01,9.94 ; J34.4 94.74,10.67 ; J34.4 94.01,11.4 ; J8.5 16.3,17.21 ; J8.5 17.38,16.13 ; J8.5 15.22,16.13 ; J8.5 16.3,15.05 ; 27.73,15.05 J8.2 ; J8.2 28.81,16.13 ; J8.2 26.65,16.13 ; J8.2 27.73,17.21 ; J35.4 106.74,10.67 ; J35.4 106.01,9.94 ; J35.4 105.28,10.67 ; J35.4 106.01,11.4 ; J1.1 10.23,87.92 ; J1.1 9.55,86.54 ; J1.1 8.87,87.92 ; 69.28,10.67 J23.6 ; J23.6 70.74,10.67 ; J23.6 70.01,9.94 ; J23.6 70.01,11.4 ; 118.01,9.94 J36.4 ; J36.4 118.74,10.67 ; J36.4 118.01,11.4 ; J36.4 117.28,10.67 ; 82.01,9.94 J32.4 ; J32.4 82.74,10.67 ; J32.4 82.01,11.4 ; J32.4 81.28,10.67 ; 15.71,19.89 SS6.1 ; SS6.1 18.49,22.67 ; SS6.1 12.93,22.67 ; SS6.1 15.71,25.45 ; v1(0.79,22.93) v1(0.79,26.74) ; 12.47,80.66 J1.2 ; J1.2 13.2,82.14 ; J1.2 13.93,80.66 ; 17.77,80.66 J1.3 ; J1.3 18.5,82.14 ; J1.3 19.23,80.66 ; 19.35,86.54 J1.5 ; J1.5 18.67,87.92 ; J1.5 20.03,87.92
  ART04 w0.508: J1.3 19.23,80.66 ; J1.3 17.77,80.66 ; J1.3 18.5,82.14 ; J1.3 18.5,79.19 ; 12.47,80.66 J1.2 ; J1.2 13.2,82.14 ; J1.2 13.93,80.66 ; J1.2 13.2,79.19 ; J3.2 3.24,41.69 ; J3.2 2.51,40.97 ; J3.2 1.78,41.69 ; J3.2 2.51,42.42 ; 12.93,22.67 SS6.1 15.71,19.89 ; J8.2 27.73,17.21 ; J8.2 26.65,16.13 ; J8.2 27.73,15.05 ; J8.2 28.81,16.13 ; J32.4 82.01,11.4 ; J32.4 82.74,10.67 ; J32.4 82.01,9.94 ; J32.4 81.28,10.67 ; 9.55,86.54 J1.1 ; J1.1 8.87,87.92 ; J1.1 10.23,87.92 ; 69.28,10.67 J23.6 ; J23.6 70.74,10.67 ; J23.6 70.01,9.94 ; 19.35,86.54 J1.5 ; J1.5 18.67,87.92 ; J1.5 20.03,87.92 ; 94.01,9.94 J34.4 ; J34.4 94.01,11.4 ; J34.4 94.74,10.67 ; J34.4 93.28,10.67 ; J3.6 3.24,33.69 ; J3.6 2.51,32.97 ; J3.6 1.78,33.69 ; J3.6 2.51,34.42 ; 21.93,75.05 J2.2 ; J2.2 22.63,74.35 ; J2.2 22.63,75.76 ; J2.2 23.33,75.05 ; 1.78,37.69 J3.4 ; J3.4 3.24,37.69 ; J3.4 2.51,36.97 ; J3.4 2.51,38.42 ; 3.05,26.57 J6.4 ; J6.4 2.14,27.47 ; J6.4 3.95,27.47 ; J6.4 3.05,28.37 ; 105.28,10.67 J35.4 ; J35.4 106.01,9.94 ; J35.4 106.74,10.67 ; J35.4 106.01,11.4 ; J36.4 118.01,11.4 ; J36.4 117.28,10.67 ; J36.4 118.01,9.94 ; J36.4 118.74,10.67 ; J8.5 16.3,17.21 ; J8.5 15.22,16.13 ; J8.5 16.3,15.05 ; J8.5 17.38,16.13 ; J7.2 18.13,75.33 ; J7.2 18.13,74.07 ; J7.2 18.75,74.7 ; 62.42,80.88 U26.2 61.84,81.46 ; v1(0.79,76.27) v1(0.79,80.08)
  BOTTOM w0.173: 79.84,59.29 78.81,59.29 78.5,59.59 78.5,61.07 78.63,61.19
  BOTTOM w0.203: 32.87,76.99 32.41,76.53 31.95,76.99 ; 32.87,76.99 31.95,76.99 ; 32.87,76.99 33.78,76.99 34.37,76.99 35.53,78.15 35.53,81.05 v1(36.02,81.53) ; v1(29.07,73.27) 28.84,73.27 27.42,74.68 27.42,76.26 28.15,76.99 31.95,76.99 ; v1(25.79,73.27) 25.9,73.38 25.9,76.85 27.46,78.41 28.52,78.41 28.52,78.41 33.71,78.41 34.11,78.82 34.11,82.12 35.76,83.77 v1(36.35,83.77)
  BOTTOM w0.254: v1(31.49,68.2) Z13.1 ; v1(28.46,68.2) Z11.1
  BOTTOM w0.305: D17.1 v1(117.73,29.84) ; J9.6 120.47,27.76 v1(120.27,27.56) ; J21.24 129.18,62.39 ; C76.2 v1(53.5,33.06) ; C103.2 v1(72.64,48.39) R104.2 ; 35.84,61.46 v1(36.51,60.78) 37.19,61.46 ; 35.84,61.46 37.19,61.46 ; 35.84,61.46 34.02,61.46 33.06,60.51 33.06,53.28 ; 23.76,57.43 v1(23.76,55.55) 23.76,54.77 24.56,53.97 29.44,53.97 30.71,55.25 30.71,58.09 v1(30.01,58.78) 30.71,59.48 30.71,62.35 29.36,63.7 29.36,67.29 v1(28.46,68.2) ; 23.76,57.43 22.29,58.9 21.2,58.9 v1(20.32,59.78) 19.76,59.22 19.76,57.34 v1(20.32,56.78) 21.85,56.78 22.35,56.29 22.35,54.34 23.99,52.7 29.14,52.7 v1(29.26,52.58) 29.84,52.58 31.23,53.97 31.7,53.97 ; 23.76,57.43 25.13,58.8 v1(25.53,58.8) ; U37.5 124.96,38.99 125.45,38.51 v1(125.45,37.21) ; D13.1 v1(117.73,23.87) ; C6.2 v1(5.69,33.01) ; C43.2 v1(5.69,36.82) ; v1(105.92,86.61) U24.2 103.65,86.61 102.77,87.49 C122.2 v1(102.74,88.39) ; D54.1 v1(110.11,16.89) ; v1(112.65,82.17) U20.3 U20.8 v1(112.65,84.71) ; 26.8,47.33 28.31,47.33 ; 26.8,47.33 24.38,47.33 23.51,46.46 22.38,46.46 v1(21.51,45.58) 20.9,46.19 20.9,47.98 v1(21.51,48.58) 21.7,48.39 26.96,48.39 ; 26.8,47.33 v1(27.56,46.57) 28.31,47.33 ; 28.31,47.33 31.35,47.33 33.06,49.04 33.06,51.89 ; D12.1 v1(117.73,22.73) ; C64.2 v1(124.71,13.21) ; 79.84,59.29 79.92,59.37 82.26,59.37 v1(83.03,58.6) 85.54,56.09 85.54,52.73 v1(86.6,51.67) 90.69,51.67 91.44,50.93 v1(91.44,47.37) v1(91.44,45.21) 91.44,31.7 92.33,30.81 93.93,30.81 94.23,31.11 94.23,32.62 v1(93.47,33.38) 93.47,36.7 92.96,37.21 v1(92.96,41.27) v1(92.96,47.37) 92.96,51.84 v1(91.62,53.19) 90.2,53.19 89.53,53.85 ; v1(10.45,40.64) U7.2 v1(8.64,40.64) ; C85.2 86.48,72.45 v1(86.92,72.9) 87.41,73.39 v1(89.55,73.39) 91.71,73.39 93.63,75.31 J15.16 ; R18.2 21.81,60.08 v1(21.51,59.78) ; 33.06,51.89 33.06,53.28 ; 33.06,51.89 v1(33.76,52.58) 33.06,53.28 ; C176.2 114.94,35.81 v1(115.12,35.99) ; D18.1 v1(117.73,30.99) 117.73,31.36 C178.2 ; v1(106.92,86.61) 108.05,86.61 109.06,85.61 C121.2 v1(109.09,84.71) ; v1(8.64,36.7) U6.2 v1(10.45,36.7) ; Q6.2 19.14,40.23 v1(19.01,40.36) ; v1(85.72,61.43) 78.87,61.43 78.63,61.19 ; v1(85.72,61.43) 85.7,61.4 85.7,60.06 86.32,59.43 ; v1(85.72,61.43) 86.14,61.85 87.5,61.85 89.04,63.39 92.31,63.39 93.2,62.5 v1(93.2,61.57) 92.47,60.83 90.81,60.83 89.41,59.43 ; 133.14,79.89 J20.25 131.99,80.86 ; C162.2 v1(69.6,33.15) ; C58.2 C57.2 C52.2 v1(17.02,35.97) ; v1(75.18,42.16) C80.2 C79.2 ; R77.2 v1(51.36,20.71) ; U8.4 27.42,33.91 v1(26.91,34.42) ; v1(95.25,83.69) U19.3 U19.8 ; v1(18.29,46.1) 18.17,46.22 C11.2 ; 26.96,48.39 28.16,48.39 ; 26.96,48.39 v1(27.56,48.98) 28.16,48.39 ; 28.16,48.39 30.91,48.39 32,49.48 32,53.67 31.7,53.97 ; 86.32,59.43 89.41,59.43 ; 86.32,59.43 86.12,59.24 v1(86.12,57.48) 86.78,56.82 86.78,53.73 v1(87.33,53.19) 87.99,53.85 89.53,53.85 ; 89.41,59.43 90.17,58.67 90.17,54.48 89.53,53.85 ; C73.2 v1(115.19,26.41) ; 37.19,61.46 38.5,61.46 40.34,63.3 40.34,63.96 v1(41.27,64.9) 41.27,64.92 40.68,65.51 39.04,65.51 38.73,65.2 38.73,65.19 38.68,65.13 38.68,63.26 37.94,62.52 33.58,62.52 32,60.95 ; C68.2 v1(39.75,20.71) ; Z3.2 v1(8.26,24.89) ; U9.3 v1(5.87,21.34) ; C90.2 v1(74.42,37.46) ; v1(123.19,58.31) 121.7,58.31 120.91,59.1 120.91,60.7 121.82,61.61 121.82,68.2 120.27,69.75 120.27,72.87 119.2,73.94 J17.6 121.94,78.23 v1(122.94,78.23) 123.51,77.65 J20.21 131.57,77.65 v1(131.6,77.62) ; C11.2 18.16,47 R5.2 ; C11.2 C10.2 18.17,48.65 v1(18.29,48.77) U2.2 v1(18.29,51.31) ; 32,60.95 32,62.86 30.67,64.19 30.67,67.38 v1(31.49,68.2) ; 32,60.95 32,54.28 31.7,53.97 ; v1(67.4,67.94) 67.52,67.82 R155.2 ; R78.2 v1(52.23,33.06) ; C105.2 v1(78.24,45.35) ; R103.2 v1(72.64,47.37) C104.2 ; R76.2 v1(66.32,33.15) ; C83.2 v1(61.59,37.43) ; R13.2 v1(15.37,55.88) 15.26,55.77 15.26,55.22 15.63,54.85 C9.2 ; v1(33.91,19.94) C70.2 32.29,20.71 31.98,21.01 31.98,25.75 31.32,26.41 v1(26.67,26.41) v1(26.67,22.22) v1(26.67,18.41) 26.67,17.19 J8.2 ; C87.2 v1(69.98,37.43) C82.2 ; R30.2 v1(21.58,42.2) ; C69.2 39.6,32.38 38.99,31.77 v1(38.99,31.36) U13.15 ; C177.2 116.97,35.84 v1(117.12,35.99) ; C54.2 v1(112.27,26.41) ; C81.2 v1(70.99,37.43) ; C4.2 v1(14.98,32.95) ; U14.5 v1(63.78,30.1) ; C75.2 v1(67.59,33.15) ; v1(61.21,33.25) 64.31,33.25 64.62,33.55 64.62,36 64.31,36.31 Y1.2 63.51,37.17 v1(63.25,37.43) C84.2 ; v1(61.21,33.25) Y1.4 ; v1(61.21,33.25) 59.87,33.25 59.56,33.55 C92.2 R98.2 v1(60.58,37.43) ; Q2.2 22.42,63.91 v1(21.81,64.51) v1(21.81,65.51) ; C55.2 33.52,68.21 v1(33.51,68.21) ; C124.2 v1(19.81,64.51) ; R153.2 v1(17.54,65.53) ; R105.2 v1(72.64,44.32) ; U9.1 v1(5.87,20.04) ; C62.2 v1(5.71,30.86) ; v1(8,55.62) 7.87,55.75 R6.2 ; D14.1 v1(117.73,25.02) ; C94.2 54.36,39.23 54.05,39.54 v1(54.05,40.67) ; R75.2 v1(65.41,20.71) ; v1(28.45,70.13) 28.46,70.12 Z11.1 ; v1(18.8,67.82) U25.2 v1(20.97,67.82) ; v1(131.75,76.12) 131.72,76.16 J20.18 ; C74.2 v1(117.73,26.41) ; R205.2 v1(99.76,47.49) ; 32.41,76.53 32.41,75.41 31.49,74.49 Z13.1 ; U10.3 v1(5.97,27.55) ; D16.1 v1(117.73,28.7) ; R116.2 v1(65.28,37.43) ; Z9.1 v1(29.07,73.27) ; U38.2 118.87,32.06 118.54,31.72 v1(118.37,31.72) ; C30.2 v1(27.69,65.53) ; C91.2 56.31,40.72 v1(56.31,41.37) 55.5,42.19 55.5,45.88 v1(56.31,46.69) 57.68,48.06 v1(57.82,48.06) 57.9,48.14 C86.2 ; C41.2 v1(14.98,36.76) ; C98.2 v1(68.96,34.92) ; C59.2 v1(7.87,16.89) ; D7.1 11.69,79.06 ; Z2.2 v1(8.26,23.49) ; C49.2 v1(5.69,40.63) ; J21.4 v1(131.63,52.39) ; D15.1 v1(117.73,27.56) ; C47.2 v1(14.98,40.64) ; U18.8 U18.3 v1(91.69,83.69) ; C123.2 v1(101.73,88.39) ; J21.23 128.87,61.89 ; U10.1 v1(8.64,27.55) ; v1(1.57,69.46) 2.07,69.97 R22.2 ; J20.4 v1(131.57,69.16) ; D53.1 v1(112.14,16.89) ; U37.8 121.44,47.01 120.83,46.4 v1(120.83,45.39) ; U15.5 v1(49.69,30.1) ; C191.2 v1(32.51,71.88) ; C187.2 v1(43.23,82.29) ; C102.2 v1(67.94,34.92) ; Z8.1 v1(25.79,73.27)
  BOTTOM w0.381: D2.2 22.63,71.7 J2.2 ; v1(98.2,69.77) 98.29,69.86 C182.2 98.29,72.66 v1(98.4,72.77) ; C66.2 v1(122.05,12.19) ; C65.2 v1(122.05,11.17) ; U12.4 0.99,76.07 v1(0.79,76.27)
  BOTTOM w0.508: v1(103.47,89.21) v1(99.66,89.21) v1(95.85,89.21) v1(92.04,89.21) v1(88.23,89.21) v1(84.42,89.21) 76.67,89.21 76.33,88.87 R111.2 ; C112.2 C117.2 ; C112.2 v1(116.59,87.63) 116.59,88.75 ; C112.2 C113.2 v1(115.57,87.63) 115.57,88.75 ; C117.2 v1(117.6,87.63) 117.6,88.75 ; C117.2 C116.2 118.63,86.61 v1(119.38,86.61) U21.2 ; J3.6 3.24,33.69 ; J3.6 2.51,32.97 ; J3.6 1.78,33.69 ; J3.6 2.51,34.42 ; 2.51,40.97 J3.2 ; J3.2 2.51,42.42 ; J3.2 1.78,41.69 ; J3.2 3.24,41.69 ; v1(136.21,29.9) v1(136.21,26.09) v1(136.21,22.28) v1(136.21,18.47) 136.21,15.24 ; 93.28,10.67 J34.4 ; J34.4 94.01,9.94 ; J34.4 94.01,11.4 ; J34.4 94.74,10.67 ; 70.01,9.94 J23.6 ; J23.6 69.28,10.67 ; J23.6 70.01,11.4 ; J23.6 70.74,10.67 ; 12.47,80.66 J1.2 ; J1.2 13.93,80.66 ; J1.2 13.2,79.19 ; J1.2 13.2,82.14 ; R114.2 75.31,88.72 74.82,89.21 v1(67.37,89.21) v1(66.37,89.21) v1(65.37,89.21) v1(61.56,89.21) v1(57.75,89.21) v1(53.94,89.21) v1(50.13,89.21) v1(46.32,89.21) v1(42.51,89.21) v1(38.7,89.21) v1(34.89,89.21) ; 129.76,8.79 v1(121.57,8.79) v1(117.76,8.79) v1(113.95,8.79) v1(110.14,8.79) v1(106.33,8.79) v1(102.52,8.79) v1(98.71,8.79) v1(94.9,8.79) v1(91.09,8.79) v1(87.28,8.79) v1(83.47,8.79) v1(79.66,8.79) v1(75.85,8.79) v1(72.04,8.79) v1(68.23,8.79) v1(64.42,8.79) v1(60.61,8.79) v1(56.8,8.79) v1(52.99,8.79) v1(49.18,8.79) v1(45.37,8.79) v1(41.56,8.79) v1(37.75,8.79) v1(33.94,8.79) v1(30.13,8.79) v1(26.32,8.79) v1(22.51,8.79) v1(18.7,8.79) v1(14.89,8.79) v1(11.08,8.79) v1(7.27,8.79) 7.24,8.79 ; J32.4 82.74,10.67 ; J32.4 81.28,10.67 ; J32.4 82.01,11.4 ; J32.4 82.01,9.94 ; J3.4 3.24,37.69 ; J3.4 1.78,37.69 ; J3.4 2.51,38.42 ; J3.4 2.51,36.97 ; J1.3 18.5,82.14 ; J1.3 19.23,80.66 ; J1.3 18.5,79.19 ; J1.3 17.77,80.66 ; J20.26 135.44,65.95 ; v1(136.21,69) v1(136.21,71.81) v1(136.21,75.62) v1(136.21,79.43) 136.21,82.73 ; J21.25 135.68,64.09 ; J35.4 106.74,10.67 ; J35.4 105.28,10.67 ; J35.4 106.01,9.94 ; J35.4 106.01,11.4 ; 8.87,87.92 J1.1 ; J1.1 10.23,87.92 ; J1.1 9.55,86.54 ; v1(136.21,37.52) v1(136.21,41.33) v1(136.21,45.14) 136.21,46.74 U37.10 136.21,47.28 ; v1(136.21,56.57) v1(136.21,60.38) ; 132.59,15.82 J9.12 ; J9.12 131.2,16.76 ; J9.12 133.97,16.76 ; 0.79,15.24 v1(0.79,15.31) v1(0.79,19.12) v1(0.79,22.93) v1(0.79,26.74) v1(0.79,30.55) v1(0.79,34.36) v1(0.79,38.17) v1(0.79,41.98) v1(0.79,45.79) v1(0.79,46.79) v1(0.79,47.79) v1(0.79,48.79) v1(0.79,49.6) v1(0.79,50.6) v1(0.79,51.6) v1(0.79,52.6) v1(0.79,53.41) v1(0.79,54.41) v1(0.79,55.22) v1(0.79,56.22) v1(0.79,57.22) v1(0.79,64.84) v1(0.79,68.65) v1(0.79,72.46) ; v1(114.9,89.21) v1(111.09,89.21) v1(107.28,89.21) 106.99,89.21 R148.2 ; J1.5 20.03,87.92 ; J1.5 18.67,87.92 ; J1.5 19.35,86.54 ; 129.73,89.21 v1(122.52,89.21) ; J5.1 26.16,30.25 ; 134.32,80.86 J20.25 133.14,81.83
  BOTTOM w0.762: v1(89.17,88.39) v1(89.17,87.39) ; J9.11 135.36,32.26 ; J9.13 124.46,19.13 v1(124.46,19.71) ; J21.26 135.37,49.19
  vias: v1(3.04,77.52) v1(4.19,62.78) v1(4.19,58.16) v1(4.28,81.66) v1(4.28,77.47) v1(4.69,41.63) v1(5.21,72.64) v1(5.21,71.5) v1(5.21,62.78) v1(5.19,59.16) v1(5.19,58.16) v1(5.33,52.77) v1(5.46,69.34) v1(5.46,68.2) v1(5.69,42.63) v1(5.69,38.82) v1(5.69,37.82) v1(5.69,35.01) v1(5.69,34.01) v1(6.22,71.5) v1(6.33,52.77) v1(6.33,51.77) v1(6.33,50.77) v1(6.33,49.77) v1(6.33,48.77) v1(6.48,68.2) v1(6.69,38.82) v1(6.69,35.01) v1(7.49,68.2) v1(7.69,38.82) v1(7.69,35.01) v1(8,54.62) v1(8.38,13.21) v1(8.51,68.2) v1(8.51,52.75) v1(8.51,51.75) v1(8.51,45.85) v1(8.64,42.67) v1(8.55,32.89) v1(8.69,38.82) v1(8.69,35.01) v1(9.53,45.85) v1(9.65,42.67) v1(9.69,38.82) v1(9.69,35.01) v1(9.69,30.2) v1(10.69,38.82) v1(10.69,35.01) v1(10.67,32.89) v1(10.69,30.2) v1(11.09,62.01) v1(11.09,61.01) v1(11.69,30.2) v1(12.09,63.01) v1(12.09,62.01) v1(12.09,61.01) v1(12.09,60.01) v1(12.19,13.21) v1(13.01,63.01) v1(13.01,62.01) v1(13.01,61.01) v1(14.99,63.99) v1(15.26,52.32) v1(15.26,51.32) v1(15.37,59.88) v1(15.37,58.88) v1(15.37,57.88) v1(15.37,56.88) v1(15.64,72.97) v1(15.64,71.97) v1(15.64,70.97) v1(16,13.21) v1(16.26,52.32) v1(16.26,51.32) v1(16.26,49.32) v1(16.26,48.32) v1(16.26,47.32) v1(17.64,72.97) v1(17.64,71.97) v1(19.05,18.41) v1(19.73,30.2) v1(19.83,26.41) v1(19.81,13.21) v1(20.73,30.2) v1(20.97,69.67) v1(21.97,69.66) v1(21.97,67.82) v1(22.13,80.3) v1(22.13,79.3) v1(22.86,22.22) v1(22.86,18.41) v1(23.13,82.3) v1(23.13,81.3) v1(23.62,13.21) v1(24.13,81.3) v1(26.35,85.47) v1(27.43,13.21) v1(28.09,30.2) v1(29.09,30.2) v1(30.53,81.3) v1(30.91,18.94) v1(31.24,13.21) v1(31.53,82.3) v1(31.53,81.3) v1(31.91,18.94) v1(32.53,82.3) v1(32.53,81.3) v1(32.91,18.94) v1(33.91,18.94) v1(34.91,18.94) v1(35.05,17.02) v1(35.05,13.21) v1(35.91,18.94) v1(37.86,82.73) v1(38.86,18.92) v1(38.86,17.02) v1(38.86,13.21) v1(41.25,13.71) v1(43.69,30.1) v1(44.4,13.66) v1(44.69,30.1) v1(45.69,30.1) v1(46.69,30.1) v1(47.69,30.1) v1(50.29,13.21) v1(54.1,13.21) v1(57,30.15) v1(57.91,13.21) v1(58.02,30.15) v1(59.03,30.15) v1(60.05,30.15) v1(61.06,30.15) v1(61.72,13.21) v1(61.87,45.45) v1(61.87,44.45) v1(61.87,43.45) v1(62.87,45.45) v1(62.87,44.45) v1(62.87,43.45) v1(63.86,45.45) v1(63.86,44.45) v1(64.64,12.19) v1(66.18,65.91) v1(66.18,64.91) v1(70.34,23.71) v1(70.34,22.71) v1(70.34,21.71) v1(71.34,23.71) v1(71.34,22.71) v1(71.34,21.71) v1(72.56,27.56) v1(73.56,27.56) v1(86.11,13.21) v1(93.98,13.21) v1(94.47,33.38) v1(95.47,33.38) v1(96.2,69.77) v1(96.52,45.16) v1(97.52,45.16) v1(98.17,11.56) v1(98.52,45.16) v1(101.47,41.25) v1(101.47,40.25) v1(102.47,41.25) v1(102.47,40.25) v1(103.06,28.03) v1(103.06,26.03) v1(103.06,25.03) v1(103.27,30.28) v1(103.27,23.03) v1(103.27,22.03) v1(103.27,20.03) v1(103.47,41.25) v1(103.47,40.25) v1(104.07,28.03) v1(104.07,26.03) v1(104.07,25.03) v1(104.27,30.28) v1(104.27,17.12) v1(105.27,30.28) v1(105.35,28.03) v1(105.35,26.03) v1(105.35,25.03) v1(105.27,17.12) v1(106.27,30.28) v1(106.28,28.03) v1(106.28,26.03) v1(106.28,25.03) v1(106.28,24.03) v1(106.28,23.03) v1(106.28,22.03) v1(106.28,21.03) v1(106.28,20.03) v1(107.27,30.28) v1(107.28,28.03) v1(108.27,30.28) v1(108.28,28.03) v1(109.27,30.28) v1(109.28,28.03) v1(110.27,30.28) v1(110.62,11.56) v1(111.27,30.28) v1(112.27,30.28) v1(112.27,29.28) v1(112.27,28.28) v1(112.88,54.05) v1(112.88,51) v1(114.91,57) v1(114.91,55.6) v1(114.88,54.08) v1(114.91,52.41) v1(115.73,44.61) v1(115.73,43.61) v1(116.73,44.61) v1(116.73,43.61) v1(117.73,51.05) v1(117.73,44.61) v1(117.73,43.61) v1(123.19,68.44) v1(123.19,66.44) v1(123.19,63.61) v1(123.19,61.61) v1(123.19,60.31) v1(123.19,59.31) v1(124.04,82.97) v1(124.04,82.17) v1(124.04,81.37) v1(124.84,82.97) v1(124.84,82.17) v1(124.84,81.37) v1(125.35,59.31) v1(125.51,64.77) v1(125.45,34.7) v1(125.45,33.7) v1(125.45,32.7) v1(125.45,31.7) v1(125.64,82.97) v1(125.64,82.17) v1(125.64,81.37) v1(126.44,32.7) v1(126.45,34.7) v1(126.45,33.7) v1(127.74,29.43) v1(127.74,28.43) v1(127.93,66.55) v1(127.93,63.89) v1(127.93,62.89) v1(127.93,60.89) v1(127.93,59.89) v1(127.91,41.63) v1(128.93,66.55) v1(128.93,63.89) v1(128.93,62.89) v1(128.93,60.89) v1(128.93,59.89) v1(128.91,44.7) v1(128.91,42.7) v1(128.91,41.63) v1(128.91,40.63) v1(128.91,38.33) v1(128.91,37.33) v1(134.44,75.31) v1(134.44,72.38) v1(135.63,52.39) v1(135.63,51.39) v1(135.63,50.39)
